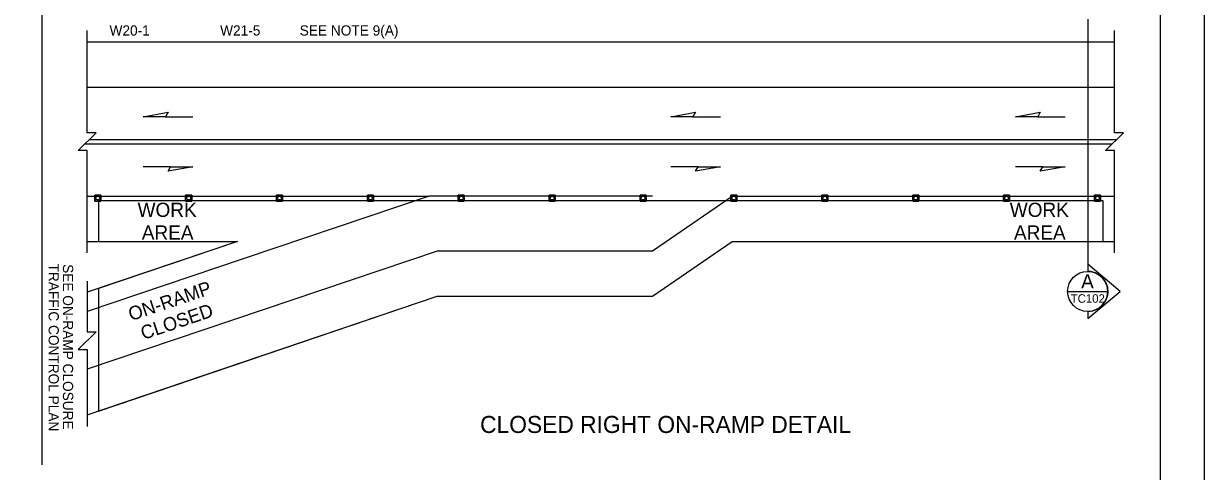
# Model space of a CAD drawing. Extents: x 99999.1 to 100055.7, y 99995 to 100013.2.
# Drawn here: x 100027.75 to 100036.06, y 100001.53 to 100004.69 of the extents above; entities that cross this region are included whole.
import ezdxf

# ---------------------------------------------------------------- set-up
doc = ezdxf.new("R2010")
doc.units = 0
for name, color, linetype in [('RD_MK_LineDblYellowCenter', 7, 'Continuous'), ('RD_MK_LineEdgeWhite', 7, 'Continuous'), ('RD_MK_LineEdgeYellow', 7, 'Continuous'), ('RD_MK_LineLane', 7, 'Continuous'), ('SH_DE_DetailHeading2Text', 7, 'Continuous'), ('SH_GI_PlotLimits', 7, 'Continuous'), ('SH_GI_SheetBorder', 7, 'Continuous'), ('SH_TI_WZSectionCut', 7, 'Continuous'), ('TR_SN_ConstructionSigns', 7, 'Continuous'), ('TR_WZ_TrafficCone', 7, 'Continuous'), ('TR_WZ_WorkAreaLabel', 7, 'Continuous'), ('TR_WZ_WorkZoneDetails', 7, 'Continuous')]:
    doc.layers.add(name, color=color, linetype=linetype)

msp = doc.modelspace()

# ---------------------------------------------------------------- linework, layer by layer
at = {"layer": 'RD_MK_LineDblYellowCenter'}
for p, q in [((100028.1785, 100003.838), (100035.4135, 100003.838)), ((100028.2115, 100003.87), (100035.4465, 100003.87))]:
    msp.add_line(p, q, dxfattribs=at)
at = {"layer": 'RD_MK_LineEdgeWhite'}
msp.add_line((100028.195, 100004.238), (100035.43, 100004.238), dxfattribs=at)
at = {"layer": 'RD_MK_LineEdgeYellow'}
for p, q in [((100028.195, 100003.47), (100029.2533, 100003.47)), ((100032.1758, 100003.086), (100032.7368, 100003.47)), ((100032.7368, 100003.47), (100035.43, 100003.47)), ((100030.6655, 100003.086), (100028.195, 100002.2517)), ((100030.6655, 100003.086), (100032.1758, 100003.086)), ((100029.2943, 100003.0282), (100028.195, 100002.657))]:
    msp.add_line(p, q, dxfattribs=at)
at = {"layer": 'RD_MK_LineLane'}
msp.add_lwpolyline([(100032.1758, 100003.47), (100030.6024, 100003.47)], dxfattribs=at)
at = {"layer": 'SH_GI_PlotLimits'}
msp.add_lwpolyline([(100019.0625, 99999.6875), (100036.0625, 99999.6875), (100036.0625, 100010.6875), (100019.0625, 100010.6875)], close=True, dxfattribs=at)
at = {"layer": 'SH_GI_SheetBorder'}
msp.add_line((100035.75, 100010.375), (100035.75, 100000), dxfattribs=at)
at = {"layer": 'SH_TI_WZSectionCut'}
for p, q in [((100035.2407, 100004.718), (100035.2407, 100002.99)), ((100035.2407, 100002.99), (100035.2407, 100002.94)), ((100035.4689, 100002.7988), (100035.2407, 100002.99)), ((100035.2407, 100002.6077), (100035.4689, 100002.7988)), ((100035.2407, 100002.6576), (100035.2407, 100002.6077))]:
    msp.add_line(p, q, dxfattribs=at)
msp.add_lwpolyline([(100035.0995, 100002.7988), (100035.3819, 100002.7988)], dxfattribs=at)
msp.add_circle((100035.2407, 100002.7988), 0.1412, dxfattribs=at)
msp.add_arc((100035.2407, 100002.7988), 0.1412, 269.99779, 90.00221, dxfattribs=at)
at = {"layer": 'TR_WZ_TrafficCone'}
for points in [[(100028.2481, 100003.478), (100028.2907, 100003.478), (100028.2907, 100003.4353), (100028.2481, 100003.4353), (100028.2481, 100003.478)], [(100028.2481, 100003.4353), (100028.2907, 100003.4353), (100028.2907, 100003.478), (100028.2481, 100003.478), (100028.2481, 100003.4353)], [(100028.8881, 100003.478), (100028.9307, 100003.478), (100028.9307, 100003.4353), (100028.8881, 100003.4353), (100028.8881, 100003.478)], [(100028.8881, 100003.4353), (100028.9307, 100003.4353), (100028.9307, 100003.478), (100028.8881, 100003.478), (100028.8881, 100003.4353)], [(100029.5281, 100003.478), (100029.5707, 100003.478), (100029.5707, 100003.4353), (100029.5281, 100003.4353), (100029.5281, 100003.478)], [(100029.5281, 100003.4353), (100029.5707, 100003.4353), (100029.5707, 100003.478), (100029.5281, 100003.478), (100029.5281, 100003.4353)], [(100030.1681, 100003.478), (100030.2107, 100003.478), (100030.2107, 100003.4353), (100030.1681, 100003.4353), (100030.1681, 100003.478)], [(100030.1681, 100003.4353), (100030.2107, 100003.4353), (100030.2107, 100003.478), (100030.1681, 100003.478), (100030.1681, 100003.4353)], [(100030.8081, 100003.478), (100030.8507, 100003.478), (100030.8507, 100003.4353), (100030.8081, 100003.4353), (100030.8081, 100003.478)], [(100030.8081, 100003.4353), (100030.8507, 100003.4353), (100030.8507, 100003.478), (100030.8081, 100003.478), (100030.8081, 100003.4353)], [(100031.4481, 100003.478), (100031.4907, 100003.478), (100031.4907, 100003.4353), (100031.4481, 100003.4353), (100031.4481, 100003.478)], [(100031.4481, 100003.4353), (100031.4907, 100003.4353), (100031.4907, 100003.478), (100031.4481, 100003.478), (100031.4481, 100003.4353)], [(100032.0881, 100003.478), (100032.1307, 100003.478), (100032.1307, 100003.4353), (100032.0881, 100003.4353), (100032.0881, 100003.478)], [(100032.0881, 100003.4353), (100032.1307, 100003.4353), (100032.1307, 100003.478), (100032.0881, 100003.478), (100032.0881, 100003.4353)], [(100032.7281, 100003.478), (100032.7707, 100003.478), (100032.7707, 100003.4353), (100032.7281, 100003.4353), (100032.7281, 100003.478)], [(100032.7281, 100003.4353), (100032.7707, 100003.4353), (100032.7707, 100003.478), (100032.7281, 100003.478), (100032.7281, 100003.4353)], [(100033.3681, 100003.478), (100033.4107, 100003.478), (100033.4107, 100003.4353), (100033.3681, 100003.4353), (100033.3681, 100003.478)], [(100033.3681, 100003.4353), (100033.4107, 100003.4353), (100033.4107, 100003.478), (100033.3681, 100003.478), (100033.3681, 100003.4353)], [(100034.0081, 100003.478), (100034.0507, 100003.478), (100034.0507, 100003.4353), (100034.0081, 100003.4353), (100034.0081, 100003.478)], [(100034.0081, 100003.4353), (100034.0507, 100003.4353), (100034.0507, 100003.478), (100034.0081, 100003.478), (100034.0081, 100003.4353)], [(100034.6481, 100003.478), (100034.6907, 100003.478), (100034.6907, 100003.4353), (100034.6481, 100003.4353), (100034.6481, 100003.478)], [(100034.6481, 100003.4353), (100034.6907, 100003.4353), (100034.6907, 100003.478), (100034.6481, 100003.478), (100034.6481, 100003.4353)], [(100035.2881, 100003.478), (100035.3307, 100003.478), (100035.3307, 100003.4353), (100035.2881, 100003.4353), (100035.2881, 100003.478)], [(100035.2881, 100003.4353), (100035.3307, 100003.4353), (100035.3307, 100003.478), (100035.2881, 100003.478), (100035.2881, 100003.4353)]]:
    msp.add_lwpolyline(points, dxfattribs=at)
for centre in [(100028.2694, 100003.4566), (100028.9094, 100003.4566), (100029.5494, 100003.4566), (100030.1894, 100003.4566), (100030.8294, 100003.4566), (100031.4694, 100003.4566), (100032.1094, 100003.4566), (100032.7494, 100003.4566), (100033.3894, 100003.4566), (100034.0294, 100003.4566), (100034.6694, 100003.4566), (100035.3094, 100003.4566)]:
    msp.add_circle(centre, 0.0133, dxfattribs=at)
at = {"layer": 'TR_WZ_WorkZoneDetails'}
for p, q in [((100027.875, 100008.9181), (100027.875, 100001.5759)), ((100028.195, 100004.558), (100035.43, 100004.558)), ((100028.7463, 100004.0305), (100028.9392, 100004.0305)), ((100032.4611, 100004.0305), (100032.654, 100004.0305)), ((100034.8886, 100004.0305), (100035.0815, 100004.0305)), ((100028.782, 100003.6774), (100028.5891, 100003.6774)), ((100032.4968, 100003.6774), (100032.3039, 100003.6774)), ((100034.9242, 100003.6774), (100034.7313, 100003.6774)), ((100029.2533, 100003.47), (100030.6024, 100003.47)), ((100030.6024, 100003.47), (100029.2943, 100003.0282)), ((100028.195, 100003.15), (100029.2533, 100003.15)), ((100029.2533, 100003.15), (100028.195, 100002.7929)), ((100032.1758, 100002.766), (100032.7368, 100003.15)), ((100032.7368, 100003.15), (100035.43, 100003.15)), ((100028.195, 100001.928), (100030.6601, 100002.766)), ((100030.6601, 100002.766), (100032.1758, 100002.766))]:
    msp.add_line(p, q, dxfattribs=at)
for points in [[(100028.195, 100003.07), (100028.195, 100003.792), (100028.131, 100003.792), (100028.259, 100003.9159), (100028.195, 100003.9159), (100028.195, 100004.638)], [(100035.43, 100003.07), (100035.43, 100003.792), (100035.366, 100003.792), (100035.494, 100003.9159), (100035.43, 100003.9159), (100035.43, 100004.638)], [(100028.195, 100002.8701), (100028.195, 100002.5136), (100028.259, 100002.5136), (100028.131, 100002.3897), (100028.195, 100002.3897), (100028.195, 100001.8453)]]:
    msp.add_lwpolyline(points, dxfattribs=at)
for points in [[(100028.5891, 100004.0305), (100028.7641, 100004.0614), (100028.7463, 100004.0305)], [(100032.3039, 100004.0305), (100032.4789, 100004.0614), (100032.4611, 100004.0305)], [(100034.7313, 100004.0305), (100034.9064, 100004.0614), (100034.8886, 100004.0305)], [(100028.9392, 100003.6774), (100028.7641, 100003.6465), (100028.782, 100003.6774)], [(100032.654, 100003.6774), (100032.4789, 100003.6465), (100032.4968, 100003.6774)], [(100035.0815, 100003.6774), (100034.9064, 100003.6465), (100034.9242, 100003.6774)], [(100028.275, 100003.438), (100028.275, 100003.15), (100029.2533, 100003.15), (100028.275, 100002.8199), (100028.275, 100002.8199), (100028.275, 100002.8199), (100028.275, 100001.9552), (100028.275, 100001.9552), (100028.275, 100001.9552), (100029.3341, 100002.3152), (100030.6601, 100002.766), (100032.1758, 100002.766), (100032.7368, 100003.15), (100035.35, 100003.15), (100035.35, 100003.438)]]:
    msp.add_lwpolyline(points, close=True, dxfattribs=at)

# ---------------------------------------------------------------- texts
at = {"layer": 'SH_DE_DetailHeading2Text'}
msp.add_text('CLOSED RIGHT ON-RAMP DETAIL', height=0.12, rotation=360, dxfattribs=at).set_placement((100030.9618, 100001.8009))
at = {"layer": 'SH_TI_WZSectionCut'}
for s, height, rotation, p in [('A', 0.1, 0.00995, (100035.1945, 100002.8195)), ('TC102', 0.06, 360, (100035.1209, 100002.7188))]:
    msp.add_text(s, height=height, rotation=rotation, dxfattribs=at).set_placement(p)
at = {"layer": 'TR_SN_ConstructionSigns'}
for s, p in [('W20-1', (100028.352, 100004.6025)), ('W21-5', (100029.131, 100004.6025)), ('SEE NOTE 9(A)', (100029.6914, 100004.6025))]:
    msp.add_text(s, height=0.072, rotation=360, dxfattribs=at).set_placement(p)
at = {"layer": 'TR_WZ_WorkAreaLabel'}
for s, p in [('WORK', (100028.5496, 100003.324)), ('WORK', (100034.6919, 100003.324)), ('AREA', (100028.5793, 100003.164)), ('AREA', (100034.7215, 100003.164))]:
    msp.add_text(s, height=0.1, dxfattribs=at).set_placement(p)
at = {"layer": 'TR_WZ_WorkZoneDetails'}
for s, height, rotation, p in [('TRAFFIC CONTROL PLAN', 0.072, 270, (100027.923, 100002.9948)), ('SEE ON-RAMP CLOSURE', 0.072, 270, (100028.0238, 100002.9908)), ('ON-RAMP', 0.096, 18.65903, (100028.5039, 100002.589)), ('ON-RAMP', 0.096, 18.65903, (100028.5039, 100002.589)), ('CLOSED', 0.096, 18.65903, (100028.5907, 100002.4562)), ('CLOSED', 0.096, 18.65903, (100028.5907, 100002.4562))]:
    msp.add_text(s, height=height, rotation=rotation, dxfattribs=at).set_placement(p)

doc.saveas('drawing.dxf')
